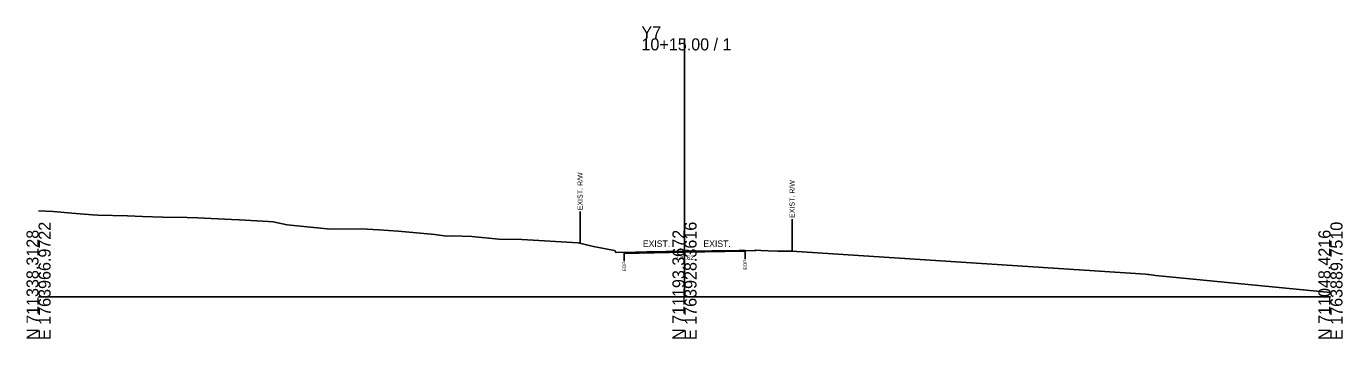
# Model space of a CAD drawing. Extents: x -26 to 2903, y -10 to 1056.
# Drawn here: x 1297.2 to 1602.8, y -9.7 to 62.9 of the extents above; entities that cross this region are included whole.
import ezdxf

# ---------------------------------------------------------------- set-up
doc = ezdxf.new("R2010")
doc.units = 0
for name, color, linetype in [('Exist Cross Section Cell', 7, 'Continuous'), ('Exist XS Center Line Elevation Label', 7, 'Continuous'), ('Exist XS Ground Line', 7, 'Continuous'), ('Old_Level_10', 7, 'Continuous'), ('Prop CMT Pvmt Course 1', 7, 'Continuous'), ('Prop CMT Pvmt Surface', 7, 'Continuous'), ('Prop XS Earthwork Shape', 7, 'Continuous'), ('Prop XS SE Text', 7, 'Continuous')]:
    doc.layers.add(name, color=color, linetype=linetype)

msp = doc.modelspace()

# ---------------------------------------------------------------- linework, layer by layer
at = {"layer": 'Exist Cross Section Cell'}
for p, q in [((1450, 0), (1450, 60.11)), ((1300, 0), (1450, 0)), ((1450, 0), (1600, 0))]:
    msp.add_line(p, q, dxfattribs=at)
at = {"layer": 'Exist XS Ground Line'}
msp.add_lwpolyline([(1300, 20.04), (1303.42, 19.84), (1304.33, 19.77), (1307.74, 19.5), (1312.51, 19.08), (1313.77, 18.99), (1320.68, 18.84), (1324.12, 18.71), (1328.85, 18.55), (1334.47, 18.5), (1337.02, 18.41), (1344.82, 17.99), (1346.6, 17.9), (1353.37, 17.55), (1354.47, 17.45), (1357.75, 16.74), (1367.78, 15.74), (1374.88, 15.87), (1379.04, 15.58), (1383.51, 15.33), (1392.06, 14.51), (1394.74, 14.14), (1396.12, 14.19), (1400.61, 14.03), (1406.92, 13.46), (1412.23, 13.34), (1425.3, 12.57), (1428.86, 11.76), (1433.72, 10.83), (1434.13, 10.33), (1438.72, 10.42), (1450, 10.62), (1462.72, 10.84), (1466.4, 10.75), (1466.45, 10.89), (1467.7, 10.8), (1469.43, 10.74), (1471.71, 10.67), (1472.84, 10.68), (1474.93, 10.68), (1554.74, 5.44), (1557.04, 5.3), (1557.57, 5.22), (1557.9, 5.2), (1559.37, 4.99), (1600, 1.06)], dxfattribs=at)
at = {"layer": 'Old_Level_10'}
for p, q in [((1425.75, 19.87), (1425.75, 12.47)), ((1474.98, 18.08), (1474.98, 10.68)), ((1436, 10.36), (1436, 8.31)), ((1464.07, 10.81), (1464.07, 8.76))]:
    msp.add_line(p, q, dxfattribs=at)
at = {"layer": 'Prop CMT Pvmt Course 1'}
for points in [[(1450, 10.63), (1436, 10.36)], [(1436, 10.1), (1450, 10.38)], [(1450, 10.63), (1464.07, 10.81)], [(1464.07, 10.68), (1450, 10.38)], [(1450, 10.38), (1450, 10.63)], [(1450, 10.38), (1450, 10.38), (1450, 10.38)]]:
    msp.add_lwpolyline(points, dxfattribs=at)
at = {"layer": 'Prop CMT Pvmt Surface'}
for points in [[(1450, 10.63), (1436, 10.36)], [(1450, 10.63), (1464.07, 10.81)]]:
    msp.add_lwpolyline(points, dxfattribs=at)
at = {"layer": 'Prop XS Earthwork Shape'}
for points in [[(1441.28, 10.47), (1436, 10.36), (1438.72, 10.42)], [(1441.28, 10.47), (1450, 10.62), (1453, 10.67), (1450, 10.63)], [(1453, 10.67), (1464.07, 10.81), (1462.72, 10.84)]]:
    msp.add_lwpolyline(points, close=True, dxfattribs=at)

# ---------------------------------------------------------------- texts
at = {"layer": 'Exist Cross Section Cell'}
for s, p in [('Y7', (1440, 60.11)), ('10+15.00 / 1', (1440, 57.31))]:
    msp.add_text(s, height=2.8, dxfattribs=at).set_placement(p)
for s, p in [('N 711338.3128', (1300, -10)), ('E 1763966.9722', (1302.8, -10)), ('N 711193.3672', (1450, -10)), ('E 1763928.3616', (1452.8, -10)), ('N 711048.4216', (1600, -10)), ('E 1763889.7510', (1602.8, -10))]:
    msp.add_text(s, height=2.8, rotation=90, dxfattribs=at).set_placement(p)
at = {"layer": 'Exist XS Center Line Elevation Label'}
msp.add_text('779.62', height=1, dxfattribs=at).set_placement((1447.89, 8.62))
at = {"layer": 'Old_Level_10'}
for s, height, p in [('EXIST. R/W', 1.181, (1426.34, 20.17)), ('EXIST. R/W', 1.181, (1475.57, 18.38)), ('EOP', 0.787, (1436.39, 5.92)), ('EOP', 0.787, (1464.46, 6.36))]:
    msp.add_text(s, height=height, rotation=90, dxfattribs=at).set_placement(p)
at = {"layer": 'Prop XS SE Text'}
for p in [(1440.32, 11.64), (1454.39, 11.64)]:
    msp.add_text('EXIST.', height=1.5, rotation=359.9114, dxfattribs=at).set_placement(p)

doc.saveas('drawing.dxf')
